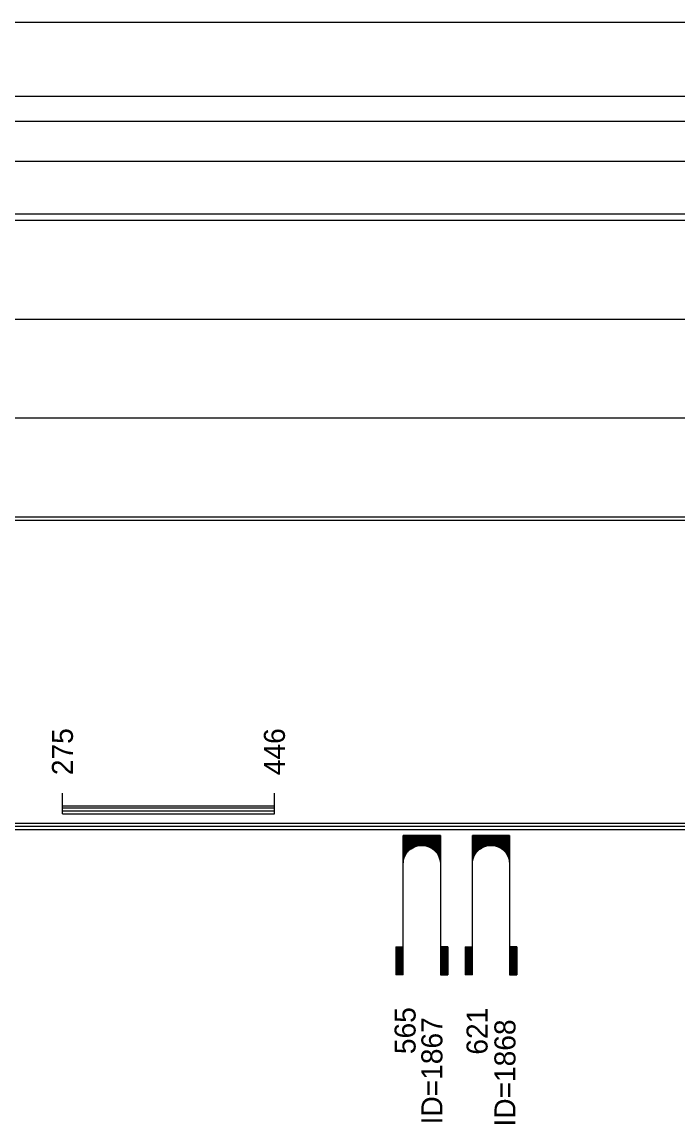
# Model space of a CAD drawing. Extents: x 2 to 10148, y 0 to 380.
# Drawn here: x 1422.5 to 1475.5, y 100.9 to 190 of the extents above; entities that cross this region are included whole.
import ezdxf

# ---------------------------------------------------------------- set-up
doc = ezdxf.new("R2010")
doc.units = 0
for name, color, linetype in [('CARA_S_OBJEKTY', 7, 'Continuous'), ('L_OBJEKTY_TEXT', 7, 'Continuous'), ('L_OBJEKTY_TVAR', 7, 'Continuous'), ('OBJEKTY_TEXT', 7, 'Continuous'), ('OBJEKTY_TVAR', 7, 'Continuous'), ('RYCHL_A', 7, 'Continuous'), ('RYCHL_B', 7, 'Continuous'), ('RYCHL_C', 7, 'Continuous'), ('RYCHL_RASTR', 7, 'Continuous')]:
    doc.layers.add(name, color=color, linetype=linetype)

msp = doc.modelspace()

# ---------------------------------------------------------------- linework, layer by layer
at = {"layer": 'CARA_S_OBJEKTY'}
for p, q in [((1245.39, 125.25), (1850.829, 125.25)), ((1245.39, 125), (1850.829, 125)), ((1245.39, 124.75), (1850.829, 124.75))]:
    msp.add_line(p, q, dxfattribs=at)
at = {"layer": 'L_OBJEKTY_TVAR'}
for p, q in [((1425.738, 126), (1425.738, 127.667)), ((1442.874, 126), (1442.874, 127.667)), ((1425.738, 126.667), (1442.874, 126.667)), ((1425.738, 126.5), (1442.874, 126.5)), ((1425.738, 126.25), (1442.874, 126.25)), ((1425.738, 126), (1442.874, 126))]:
    msp.add_line(p, q, dxfattribs=at)
at = {"layer": 'OBJEKTY_TVAR'}
for p, q in [((1453.289, 113), (1453.289, 124.25)), ((1456.289, 124.25), (1453.289, 124.25)), ((1453.289, 124.17), (1456.289, 124.17)), ((1453.289, 124.1), (1456.289, 124.1)), ((1453.289, 124.02), (1456.289, 124.02)), ((1453.289, 123.95), (1456.289, 123.95)), ((1453.289, 123.87), (1456.289, 123.87)), ((1453.289, 123.8), (1456.289, 123.8)), ((1456.289, 124.25), (1456.289, 113)), ((1458.883, 113), (1458.883, 124.25)), ((1461.883, 124.25), (1458.883, 124.25)), ((1458.883, 124.17), (1461.883, 124.17)), ((1458.883, 124.1), (1461.883, 124.1)), ((1458.883, 124.02), (1461.883, 124.02)), ((1458.883, 123.95), (1461.883, 123.95)), ((1458.883, 123.87), (1461.883, 123.87)), ((1458.883, 123.8), (1461.883, 123.8)), ((1461.883, 124.25), (1461.883, 113)), ((1453.289, 123.72), (1456.289, 123.72)), ((1453.289, 123.65), (1456.289, 123.65)), ((1453.289, 123.57), (1456.289, 123.57)), ((1453.289, 123.5), (1456.289, 123.5)), ((1453.289, 123.42), (1454.449, 123.42)), ((1453.289, 123.35), (1454.209, 123.35)), ((1453.289, 123.27), (1454.059, 123.27)), ((1453.289, 123.2), (1453.939, 123.2)), ((1453.289, 123.12), (1453.839, 123.12)), ((1453.289, 123.05), (1453.749, 123.05)), ((1453.289, 122.97), (1453.679, 122.97)), ((1453.289, 122.9), (1453.619, 122.9)), ((1453.509, 122.75), (1453.619, 122.9)), ((1453.619, 122.9), (1453.749, 123.05)), ((1453.749, 123.05), (1453.829, 123.12)), ((1453.829, 123.12), (1453.929, 123.19)), ((1453.929, 123.19), (1454.059, 123.27)), ((1454.059, 123.27), (1454.209, 123.35)), ((1454.209, 123.35), (1454.449, 123.42)), ((1454.449, 123.42), (1454.659, 123.46)), ((1454.659, 123.46), (1454.909, 123.46)), ((1454.909, 123.46), (1455.049, 123.44)), ((1455.049, 123.44), (1455.129, 123.42)), ((1455.129, 123.42), (1456.289, 123.42)), ((1455.129, 123.42), (1455.369, 123.35)), ((1455.369, 123.35), (1456.289, 123.35)), ((1455.369, 123.35), (1455.519, 123.27)), ((1455.519, 123.27), (1456.289, 123.27)), ((1455.519, 123.27), (1455.639, 123.2)), ((1455.639, 123.2), (1456.289, 123.2)), ((1455.639, 123.2), (1455.739, 123.12)), ((1455.739, 123.12), (1456.289, 123.12)), ((1455.739, 123.12), (1455.829, 123.05)), ((1455.829, 123.05), (1456.289, 123.05)), ((1455.829, 123.05), (1455.899, 122.97)), ((1455.899, 122.97), (1456.289, 122.97)), ((1455.899, 122.97), (1455.959, 122.9)), ((1455.959, 122.9), (1456.279, 122.9)), ((1455.959, 122.9), (1456.019, 122.82)), ((1458.883, 123.72), (1461.883, 123.72)), ((1458.883, 123.65), (1461.883, 123.65)), ((1458.883, 123.57), (1461.883, 123.57)), ((1458.883, 123.5), (1461.883, 123.5)), ((1458.883, 123.42), (1460.043, 123.42)), ((1458.883, 123.35), (1459.803, 123.35)), ((1458.883, 123.27), (1459.653, 123.27)), ((1458.883, 123.2), (1459.533, 123.2)), ((1458.883, 123.12), (1459.433, 123.12)), ((1458.883, 123.05), (1459.343, 123.05)), ((1458.883, 122.97), (1459.273, 122.97)), ((1458.883, 122.9), (1459.213, 122.9)), ((1459.103, 122.75), (1459.213, 122.9)), ((1459.213, 122.9), (1459.343, 123.05)), ((1459.343, 123.05), (1459.423, 123.12)), ((1459.423, 123.12), (1459.523, 123.19)), ((1459.523, 123.19), (1459.653, 123.27)), ((1459.653, 123.27), (1459.803, 123.35)), ((1459.803, 123.35), (1460.043, 123.42)), ((1460.043, 123.42), (1460.253, 123.46)), ((1460.253, 123.46), (1460.503, 123.46)), ((1460.503, 123.46), (1460.643, 123.44)), ((1460.643, 123.44), (1460.723, 123.42)), ((1460.723, 123.42), (1461.883, 123.42)), ((1460.723, 123.42), (1460.963, 123.35)), ((1460.963, 123.35), (1461.883, 123.35)), ((1460.963, 123.35), (1461.113, 123.27)), ((1461.113, 123.27), (1461.883, 123.27)), ((1461.113, 123.27), (1461.233, 123.2)), ((1461.233, 123.2), (1461.883, 123.2)), ((1461.233, 123.2), (1461.333, 123.12)), ((1461.333, 123.12), (1461.883, 123.12)), ((1461.333, 123.12), (1461.423, 123.05)), ((1461.423, 123.05), (1461.883, 123.05)), ((1461.423, 123.05), (1461.493, 122.97)), ((1461.493, 122.97), (1461.883, 122.97)), ((1461.493, 122.97), (1461.553, 122.9)), ((1461.553, 122.9), (1461.873, 122.9)), ((1461.553, 122.9), (1461.613, 122.82)), ((1453.289, 122.82), (1453.559, 122.82)), ((1453.289, 122.75), (1453.509, 122.75)), ((1453.289, 122.67), (1453.469, 122.67)), ((1453.289, 122.6), (1453.429, 122.6)), ((1453.289, 122.52), (1453.399, 122.52)), ((1453.289, 122.45), (1453.369, 122.45)), ((1453.289, 122.37), (1453.349, 122.37)), ((1453.289, 122.3), (1453.329, 122.3)), ((1453.289, 122.22), (1453.309, 122.22)), ((1453.289, 122.15), (1453.299, 122.15)), ((1453.289, 121.97), (1453.299, 122.11)), ((1453.299, 122.11), (1453.319, 122.28)), ((1453.319, 122.28), (1453.369, 122.46)), ((1453.369, 122.46), (1453.439, 122.61)), ((1453.439, 122.61), (1453.509, 122.75)), ((1456.019, 122.82), (1456.289, 122.82)), ((1456.019, 122.82), (1456.109, 122.67)), ((1456.069, 122.75), (1456.289, 122.75)), ((1456.109, 122.67), (1456.289, 122.67)), ((1456.109, 122.67), (1456.179, 122.52)), ((1456.149, 122.6), (1456.289, 122.6)), ((1456.179, 122.52), (1456.289, 122.52)), ((1456.179, 122.52), (1456.229, 122.37)), ((1456.209, 122.45), (1456.289, 122.45)), ((1456.229, 122.37), (1456.289, 122.37)), ((1456.229, 122.37), (1456.269, 122.22)), ((1456.249, 122.3), (1456.289, 122.3)), ((1456.269, 122.22), (1456.289, 122.22)), ((1456.269, 122.22), (1456.289, 121.97)), ((1456.279, 122.15), (1456.289, 122.15)), ((1458.883, 122.82), (1459.153, 122.82)), ((1458.883, 122.75), (1459.103, 122.75)), ((1458.883, 122.67), (1459.063, 122.67)), ((1458.883, 122.6), (1459.023, 122.6)), ((1458.883, 122.52), (1458.993, 122.52)), ((1458.883, 122.45), (1458.963, 122.45)), ((1458.883, 122.37), (1458.943, 122.37)), ((1458.883, 122.3), (1458.923, 122.3)), ((1458.883, 122.22), (1458.903, 122.22)), ((1458.883, 122.15), (1458.893, 122.15)), ((1458.883, 121.97), (1458.893, 122.11)), ((1458.893, 122.11), (1458.913, 122.28)), ((1458.913, 122.28), (1458.963, 122.46)), ((1458.963, 122.46), (1459.033, 122.61)), ((1459.033, 122.61), (1459.103, 122.75)), ((1461.613, 122.82), (1461.883, 122.82)), ((1461.613, 122.82), (1461.703, 122.67)), ((1461.663, 122.75), (1461.883, 122.75)), ((1461.703, 122.67), (1461.883, 122.67)), ((1461.703, 122.67), (1461.773, 122.52)), ((1461.743, 122.6), (1461.883, 122.6)), ((1461.773, 122.52), (1461.883, 122.52)), ((1461.773, 122.52), (1461.823, 122.37)), ((1461.803, 122.45), (1461.883, 122.45)), ((1461.823, 122.37), (1461.883, 122.37)), ((1461.823, 122.37), (1461.863, 122.22)), ((1461.843, 122.3), (1461.883, 122.3)), ((1461.863, 122.22), (1461.883, 122.22)), ((1461.863, 122.22), (1461.883, 121.97)), ((1461.873, 122.15), (1461.883, 122.15)), ((1452.689, 115.25), (1453.289, 115.25)), ((1452.689, 115.25), (1452.689, 113)), ((1452.759, 115.25), (1452.759, 113)), ((1452.839, 115.25), (1452.839, 113)), ((1452.909, 115.25), (1452.909, 113)), ((1452.989, 115.25), (1452.989, 113)), ((1453.059, 115.25), (1453.059, 113)), ((1453.139, 115.25), (1453.139, 113)), ((1453.209, 115.25), (1453.209, 113)), ((1456.889, 115.25), (1456.289, 115.25)), ((1456.369, 115.25), (1456.369, 113)), ((1456.439, 115.25), (1456.439, 113)), ((1456.519, 115.25), (1456.519, 113)), ((1456.589, 115.25), (1456.589, 113)), ((1456.669, 115.25), (1456.669, 113)), ((1456.739, 115.25), (1456.739, 113)), ((1456.819, 115.25), (1456.819, 113)), ((1456.889, 115.25), (1456.889, 113)), ((1458.283, 115.25), (1458.883, 115.25)), ((1458.283, 115.25), (1458.283, 113)), ((1458.353, 115.25), (1458.353, 113)), ((1458.433, 115.25), (1458.433, 113)), ((1458.503, 115.25), (1458.503, 113)), ((1458.583, 115.25), (1458.583, 113)), ((1458.653, 115.25), (1458.653, 113)), ((1458.733, 115.25), (1458.733, 113)), ((1458.803, 115.25), (1458.803, 113)), ((1462.483, 115.25), (1461.883, 115.25)), ((1461.963, 115.25), (1461.963, 113)), ((1462.033, 115.25), (1462.033, 113)), ((1462.113, 115.25), (1462.113, 113)), ((1462.183, 115.25), (1462.183, 113)), ((1462.263, 115.25), (1462.263, 113)), ((1462.333, 115.25), (1462.333, 113)), ((1462.413, 115.25), (1462.413, 113)), ((1462.483, 115.25), (1462.483, 113)), ((1453.289, 113), (1452.689, 113)), ((1456.289, 113), (1456.889, 113)), ((1458.883, 113), (1458.283, 113)), ((1461.883, 113), (1462.483, 113))]:
    msp.add_line(p, q, dxfattribs=at)
at = {"layer": 'RYCHL_A'}
msp.add_line((1403.283, 174.5), (1850.83, 174.5), dxfattribs=at)
at = {"layer": 'RYCHL_B'}
msp.add_line((1245.693, 178.75), (1512.396, 178.75), dxfattribs=at)
at = {"layer": 'RYCHL_C'}
msp.add_line((1089.267, 184), (1511.665, 184), dxfattribs=at)
at = {"layer": 'RYCHL_RASTR'}
for p, q in [((1245.39, 190), (1854.257, 190)), ((1245.39, 182), (1853.573, 182)), ((1245.39, 174), (1854.627, 174)), ((1245.39, 166), (1853.774, 166)), ((1245.39, 158), (1853.785, 158)), ((1245.39, 150), (1850.829, 150)), ((1245.39, 149.75), (1850.829, 149.75))]:
    msp.add_line(p, q, dxfattribs=at)

# ---------------------------------------------------------------- texts
at = {"layer": 'L_OBJEKTY_TEXT'}
for s, p in [('275', (1426.588, 129.133)), ('446', (1443.724, 129.133))]:
    msp.add_text(s, height=1.7, rotation=90, dxfattribs=at).set_placement(p)
at = {"layer": 'OBJEKTY_TEXT'}
for s, p in [('565', (1454.288, 106.589)), ('621', (1460.107, 106.545)), ('ID=1867', (1456.454, 100.91)), ('ID=1868', (1462.36, 100.735))]:
    msp.add_text(s, height=1.7, rotation=90, dxfattribs=at).set_placement(p)

doc.saveas('drawing.dxf')
